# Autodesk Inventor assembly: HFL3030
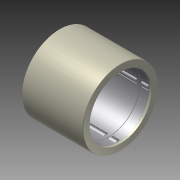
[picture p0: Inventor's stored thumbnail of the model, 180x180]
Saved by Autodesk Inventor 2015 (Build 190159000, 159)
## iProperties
Company: TraceParts S.A.
Created: 2012-12
Part Number: HFL3030
Checked By: TraceParts S.A.
Catalog Web Link: www.traceparts.com
Description: Freilauf
Vendor: Schaeffler Technologies AG & Co. KG
Document SubType Name: Assembly
Designer: TraceParts
DESIGN: Freilauf
REFERENCE: HFL3030
SELECTION: HFL3030
SUPPLIER: Schaeffler Technologies AG & Co. KG
Title: Freilauf
Author: TraceParts
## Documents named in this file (8)
- C:\Users\Andrew Almeida\Documents\Projeto WS2015\WS2015 CAD Data ANLAS\01\Pneumatic System\Engine\Pneumatikus hajtás\Szabadonfutó\inafag_hfl3030_elarmg9trzt6j3zc3til76m2w.iam
- C:\Users\Andrew Almeida\Documents\Projeto WS2015\WS2015 CAD Data ANLAS\01\Pneumatic System\Engine\Pneumatikus hajtás\Szabadonfutó\inafag_hfl3030_elarmg9trzt6j3zc3til76m2w_07.ipt
- C:\Users\Andrew Almeida\Documents\Projeto WS2015\WS2015 CAD Data ANLAS\01\Pneumatic System\Engine\Pneumatikus hajtás\Szabadonfutó\inafag_hfl3030_elarmg9trzt6j3zc3til76m2w_06.ipt
- C:\Users\Andrew Almeida\Documents\Projeto WS2015\WS2015 CAD Data ANLAS\01\Pneumatic System\Engine\Pneumatikus hajtás\Szabadonfutó\inafag_hfl3030_elarmg9trzt6j3zc3til76m2w_05.ipt
- C:\Users\Andrew Almeida\Documents\Projeto WS2015\WS2015 CAD Data ANLAS\01\Pneumatic System\Engine\Pneumatikus hajtás\Szabadonfutó\inafag_hfl3030_elarmg9trzt6j3zc3til76m2w_04.ipt
- C:\Users\Andrew Almeida\Documents\Projeto WS2015\WS2015 CAD Data ANLAS\01\Pneumatic System\Engine\Pneumatikus hajtás\Szabadonfutó\inafag_hfl3030_elarmg9trzt6j3zc3til76m2w_03.ipt
- C:\Users\Andrew Almeida\Documents\Projeto WS2015\WS2015 CAD Data ANLAS\01\Pneumatic System\Engine\Pneumatikus hajtás\Szabadonfutó\inafag_hfl3030_elarmg9trzt6j3zc3til76m2w_02.ipt
- C:\Users\Andrew Almeida\Documents\Projeto WS2015\WS2015 CAD Data ANLAS\01\Pneumatic System\Engine\Pneumatikus hajtás\Szabadonfutó\inafag_hfl3030_elarmg9trzt6j3zc3til76m2w_01.ipt
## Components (7 placed, 7 different names)
1. inafag_hfl3030_elarmg9trzt6j3zc3til76m2w_07:1
2. inafag_hfl3030_elarmg9trzt6j3zc3til76m2w_06:1
3. inafag_hfl3030_elarmg9trzt6j3zc3til76m2w_05:1
4. inafag_hfl3030_elarmg9trzt6j3zc3til76m2w_04:1
5. inafag_hfl3030_elarmg9trzt6j3zc3til76m2w_03:1
6. inafag_hfl3030_elarmg9trzt6j3zc3til76m2w_02:1
7. inafag_hfl3030_elarmg9trzt6j3zc3til76m2w_01:1
